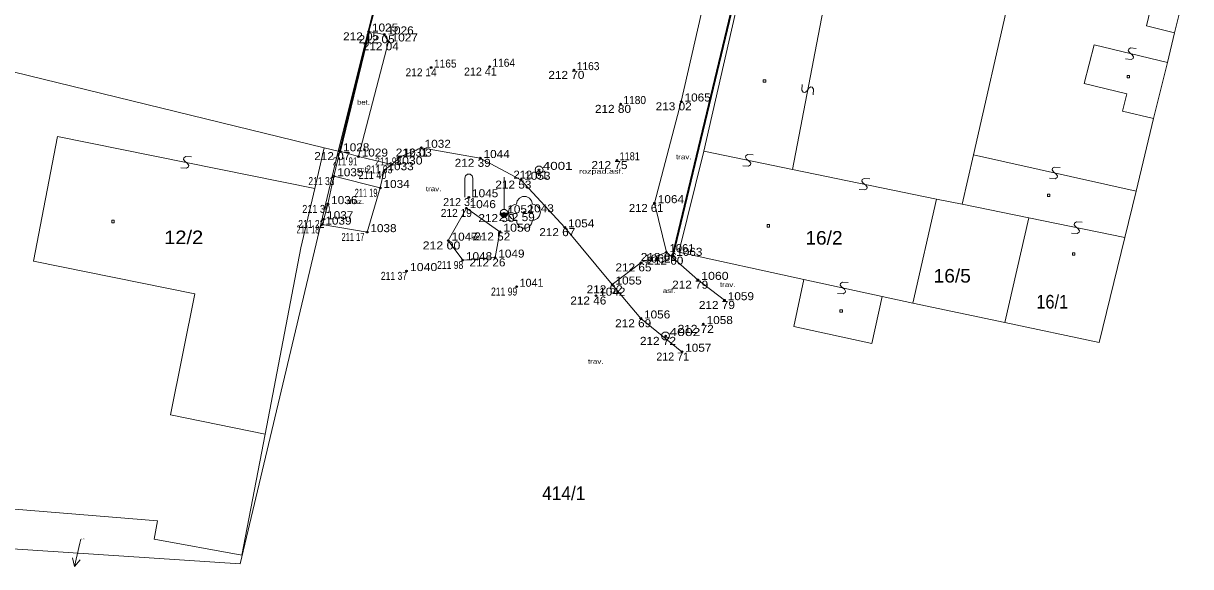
# Model space of a CAD drawing. Extents: x -736847 to -736508, y -1028413 to -1028271.
# Drawn here: x -736680.1 to -736607.2, y -1028365.5 to -1028331.6 of the extents above; entities that cross this region are included whole.
import ezdxf
from ezdxf.enums import TextEntityAlignment as Align

# ---------------------------------------------------------------- set-up
doc = ezdxf.new("R2010")
doc.units = 0
doc.header["$LTSCALE"] = 0.2
doc.header["$PDMODE"] = 32
doc.header["$PDSIZE"] = 0.1
for name, color, linetype, lineweight in [('1', 7, 'Continuous', 13), ('11', 7, 'Continuous', 13), ('12', 7, 'Continuous', 13), ('13', 7, 'Continuous', 13), ('2', 7, 'Continuous', 13), ('6', 7, 'Continuous', 35), ('63', 7, 'Continuous', 13), ('8', 7, 'Continuous', 13)]:
    doc.layers.add(name, color=color, linetype=linetype, lineweight=lineweight)
for name, color, linetype in [('34', 7, 'Continuous'), ('35', 7, 'Continuous'), ('36', 7, 'Continuous'), ('60', 7, 'Continuous')]:
    doc.layers.add(name, color=color, linetype=linetype)

msp = doc.modelspace()

# ---------------------------------------------------------------- linework, layer by layer
at = {"layer": '1'}
for p, q in [((-736657.21, -1028326.51), (-736660.48, -1028339.57)), ((-736607.24, -1028328.06), (-736608.24, -1028332.18)), ((-736620.8, -1028339.79), (-736618.51, -1028329.76)), ((-736632.11, -1028340.7), (-736630.19, -1028330.74)), ((-736608.24, -1028332.18), (-736608.69, -1028334.03)), ((-736613.26, -1028332.92), (-736613.88, -1028335.34)), ((-736608.69, -1028334.03), (-736613.26, -1028332.92)), ((-736661.35, -1028339.36), (-736682.13, -1028334.28)), ((-736608.69, -1028334.03), (-736609.55, -1028337.53)), ((-736613.88, -1028335.34), (-736611.23, -1028335.99)), ((-736611.49, -1028337.06), (-736611.23, -1028335.99)), ((-736609.55, -1028337.53), (-736611.49, -1028337.06)), ((-736609.55, -1028337.53), (-736610.65, -1028342.05)), ((-736678, -1028338.64), (-736679.51, -1028346.43)), ((-736661.94, -1028341.89), (-736678, -1028338.64)), ((-736661.35, -1028339.36), (-736660.48, -1028339.57)), ((-736639.21, -1028345.87), (-736637.65, -1028339.56)), ((-736632.11, -1028340.7), (-736637.65, -1028339.56)), ((-736620.8, -1028339.79), (-736621.5, -1028342.88)), ((-736620.8, -1028339.79), (-736610.65, -1028342.05)), ((-736632.11, -1028340.7), (-736623.11, -1028342.55)), ((-736610.65, -1028342.05), (-736611.36, -1028344.96)), ((-736624.58, -1028349.06), (-736623.11, -1028342.55)), ((-736623.11, -1028342.55), (-736621.5, -1028342.88)), ((-736617.34, -1028343.73), (-736621.5, -1028342.88)), ((-736618.84, -1028350.26), (-736617.34, -1028343.73)), ((-736617.34, -1028343.73), (-736611.36, -1028344.96)), ((-736612.96, -1028351.52), (-736611.36, -1028344.96)), ((-736631.4, -1028347.58), (-736639.21, -1028345.87)), ((-736631.4, -1028347.58), (-736632.03, -1028350.51)), ((-736626.51, -1028348.64), (-736631.4, -1028347.58)), ((-736624.58, -1028349.06), (-736618.84, -1028350.26)), ((-736618.84, -1028350.26), (-736612.96, -1028351.52)), ((-736671.76, -1028362.66), (-736680.68, -1028361.93)), ((-736671.97, -1028363.79), (-736671.76, -1028362.66)), ((-736676.54, -1028363.8), (-736676.6, -1028364.05)), ((-736666.5, -1028364.79), (-736671.97, -1028363.79))]:
    msp.add_line(p, q, dxfattribs=at)
for points in [[(-736637.65, -1028339.56), (-736635.35, -1028329.52), (-736634.27, -1028325.67)], [(-736608.24, -1028332.18), (-736609.99, -1028331.73), (-736609.74, -1028330.69), (-736615.03, -1028329.39), (-736615.32, -1028330.54), (-736618.51, -1028329.76)], [(-736661.35, -1028339.36), (-736661.94, -1028341.89), (-736662.8, -1028345.59)], [(-736660.48, -1028339.57), (-736666.59, -1028365.34), (-736681.13, -1028364.37)], [(-736662.8, -1028345.59), (-736665.04, -1028357.23), (-736666.5, -1028364.79)], [(-736665.04, -1028357.23), (-736670.95, -1028356.03), (-736669.42, -1028348.48), (-736679.51, -1028346.43)], [(-736632.03, -1028350.51), (-736627.15, -1028351.57), (-736626.51, -1028348.64), (-736624.58, -1028349.06)]]:
    msp.add_lwpolyline(points, dxfattribs=at)
at = {"layer": '11'}
for p, q in [((-736647.955, -1028340.73), (-736647.905, -1028340.73)), ((-736640.055, -1028351.11), (-736640.005, -1028351.11))]:
    msp.add_line(p, q, dxfattribs=at)
for points in [[(-736647.855, -1028340.49), (-736647.73, -1028340.58), (-736647.68, -1028340.725), (-736647.73, -1028340.87), (-736647.855, -1028340.96), (-736648.01, -1028340.96), (-736648.135, -1028340.87), (-736648.185, -1028340.725), (-736648.135, -1028340.58), (-736648.01, -1028340.49)], [(-736639.955, -1028350.87), (-736639.83, -1028350.96), (-736639.78, -1028351.105), (-736639.83, -1028351.25), (-736639.955, -1028351.34), (-736640.11, -1028351.34), (-736640.235, -1028351.25), (-736640.285, -1028351.105), (-736640.235, -1028350.96), (-736640.11, -1028350.87)]]:
    msp.add_lwpolyline(points, close=True, dxfattribs=at)
at = {"layer": '12'}
for points in [[(-736647.85, -1028343.38), (-736647.899, -1028343.597), (-736648.038, -1028343.771), (-736648.239, -1028343.867), (-736648.35, -1028343.88), (-736648.399, -1028344.097), (-736648.538, -1028344.271), (-736648.739, -1028344.367), (-736648.961, -1028344.367), (-736649.161, -1028344.271), (-736649.3, -1028344.097), (-736649.35, -1028343.88), (-736649.461, -1028343.867), (-736649.661, -1028343.771), (-736649.8, -1028343.597), (-736649.85, -1028343.38), (-736649.8, -1028343.163), (-736649.661, -1028342.989), (-736649.461, -1028342.892), (-736649.35, -1028342.88), (-736649.3, -1028342.663), (-736649.161, -1028342.489), (-736648.961, -1028342.392), (-736648.739, -1028342.392), (-736648.538, -1028342.489), (-736648.399, -1028342.663), (-736648.35, -1028342.88), (-736648.239, -1028342.892), (-736648.038, -1028342.989), (-736647.899, -1028343.163)], [(-736652.47, -1028343.12), (-736653.6, -1028345.15), (-736652.7, -1028346.37), (-736650.68, -1028346.21), (-736650.38, -1028344.59)]]:
    msp.add_lwpolyline(points, close=True, dxfattribs=at)
msp.add_lwpolyline([(-736648.875, -1028343.38), (-736648.85, -1028343.38), (-736648.825, -1028343.38)], dxfattribs=at)
at = {"layer": '13'}
msp.add_line((-736655.28, -1028339.35), (-736651.6, -1028339.99), dxfattribs=at)
for points in [[(-736636.35, -1028348.87), (-736638.02, -1028347.6), (-736639.98, -1028345.87), (-736640.72, -1028342.81), (-736639.05, -1028336.46), (-736637.34, -1028328.99)], [(-736658.57, -1028332.09), (-736657.6, -1028332.27), (-736657.34, -1028332.71), (-736659.21, -1028339.9)], [(-736657.13, -1028340.4), (-736656.57, -1028339.9), (-736655.28, -1028339.35)], [(-736651.6, -1028339.99), (-736649.06, -1028341.35), (-736646.32, -1028344.32), (-736643.36, -1028347.89), (-736641.58, -1028350.01), (-736639.01, -1028352.09)], [(-736657.85, -1028341.86), (-736658.67, -1028344.62), (-736661.48, -1028344.15)], [(-736643.36, -1028347.89), (-736641.56, -1028346.52), (-736639.98, -1028345.87)]]:
    msp.add_lwpolyline(points, dxfattribs=at)
at = {"layer": '2'}
msp.add_line((-736676.934, -1028365.512), (-736677.066, -1028364.969), dxfattribs=at)
for points in [[(-736610.637, -1028333.145), (-736610.989, -1028333.111), (-736611.11, -1028333.184), (-736611.133, -1028333.282), (-736611.06, -1028333.402), (-736610.889, -1028333.547), (-736610.816, -1028333.667), (-736610.839, -1028333.765), (-736610.96, -1028333.838), (-736611.312, -1028333.804)], [(-736631.495, -1028335.398), (-736631.512, -1028335.751), (-736631.433, -1028335.869), (-736631.335, -1028335.888), (-736631.218, -1028335.808), (-736631.081, -1028335.631), (-736630.964, -1028335.552), (-736630.866, -1028335.57), (-736630.787, -1028335.688), (-736630.804, -1028336.041)], [(-736669.645, -1028339.922), (-736669.998, -1028339.902), (-736670.116, -1028339.98), (-736670.136, -1028340.078), (-736670.058, -1028340.196), (-736669.881, -1028340.333), (-736669.803, -1028340.451), (-736669.823, -1028340.549), (-736669.941, -1028340.627), (-736670.294, -1028340.607)], [(-736634.554, -1028339.788), (-736634.907, -1028339.767), (-736635.025, -1028339.844), (-736635.045, -1028339.942), (-736634.967, -1028340.06), (-736634.792, -1028340.199), (-736634.714, -1028340.317), (-736634.734, -1028340.415), (-736634.852, -1028340.492), (-736635.205, -1028340.471)], [(-736615.394, -1028340.583), (-736615.746, -1028340.556), (-736615.865, -1028340.632), (-736615.887, -1028340.73), (-736615.811, -1028340.849), (-736615.638, -1028340.99), (-736615.562, -1028341.109), (-736615.584, -1028341.207), (-736615.703, -1028341.283), (-736616.055, -1028341.256)], [(-736627.284, -1028341.283), (-736627.637, -1028341.262), (-736627.755, -1028341.339), (-736627.775, -1028341.437), (-736627.697, -1028341.555), (-736627.522, -1028341.694), (-736627.444, -1028341.812), (-736627.464, -1028341.91), (-736627.582, -1028341.987), (-736627.935, -1028341.966)], [(-736614.024, -1028344.003), (-736614.377, -1028343.982), (-736614.495, -1028344.059), (-736614.515, -1028344.157), (-736614.437, -1028344.275), (-736614.262, -1028344.414), (-736614.184, -1028344.532), (-736614.204, -1028344.63), (-736614.322, -1028344.707), (-736614.675, -1028344.686)], [(-736628.625, -1028347.772), (-736628.978, -1028347.746), (-736629.097, -1028347.823), (-736629.118, -1028347.921), (-736629.042, -1028348.039), (-736628.867, -1028348.18), (-736628.791, -1028348.298), (-736628.812, -1028348.396), (-736628.931, -1028348.473), (-736629.284, -1028348.447)], [(-736676.6, -1028364.05), (-736676.934, -1028365.512), (-736676.579, -1028365.08)]]:
    msp.add_lwpolyline(points, dxfattribs=at)
for points in [[(-736633.93, -1028335.1), (-736633.78, -1028335.1), (-736633.78, -1028335.25), (-736633.93, -1028335.25)], [(-736611.21, -1028334.83), (-736611.06, -1028334.83), (-736611.06, -1028334.98), (-736611.21, -1028334.98)], [(-736616.18, -1028342.25), (-736616.03, -1028342.25), (-736616.03, -1028342.4), (-736616.18, -1028342.4)], [(-736674.61, -1028343.88), (-736674.46, -1028343.88), (-736674.46, -1028344.03), (-736674.61, -1028344.03)], [(-736633.69, -1028344.15), (-736633.54, -1028344.15), (-736633.54, -1028344.3), (-736633.69, -1028344.3)], [(-736614.62, -1028345.91), (-736614.47, -1028345.91), (-736614.47, -1028346.06), (-736614.62, -1028346.06)], [(-736629.14, -1028349.47), (-736628.99, -1028349.47), (-736628.99, -1028349.62), (-736629.14, -1028349.62)]]:
    msp.add_lwpolyline(points, close=True, dxfattribs=at)
at = {"layer": '34'}
for p in [(-736658.57, -1028332.09), (-736657.6, -1028332.27), (-736657.34, -1028332.71), (-736654.67, -1028334.34), (-736651.02, -1028334.29), (-736645.75, -1028334.5), (-736642.84, -1028336.62), (-736639.05, -1028336.46), (-736655.28, -1028339.35), (-736660.37, -1028339.57), (-736659.21, -1028339.9), (-736656.57, -1028339.9), (-736651.6, -1028339.99), (-736643.06, -1028340.13), (-736657.6, -1028340.75), (-736657.13, -1028340.4), (-736647.93, -1028340.73), (-736660.74, -1028341.13), (-736649.06, -1028341.35), (-736657.85, -1028341.86), (-736652.32, -1028342.44), (-736661.12, -1028342.87), (-736652.47, -1028343.12), (-736640.72, -1028342.81), (-736661.37, -1028343.81), (-736650.12, -1028343.44), (-736648.85, -1028343.38), (-736661.48, -1028344.15), (-736658.67, -1028344.62), (-736650.38, -1028344.59), (-736646.32, -1028344.32), (-736653.6, -1028345.15), (-736639.98, -1028345.87), (-736639.57, -1028346.1), (-736652.7, -1028346.37), (-736650.68, -1028346.21), (-736641.56, -1028346.52), (-736656.21, -1028347.05), (-736649.33, -1028348.03), (-736643.36, -1028347.89), (-736638.02, -1028347.6), (-736644.38, -1028348.59), (-736636.35, -1028348.87), (-736641.58, -1028350.01), (-736637.67, -1028350.36), (-736640.03, -1028351.11), (-736639.01, -1028352.09)]:
    msp.add_point(p, dxfattribs=at)
at = {"layer": '6'}
for p, q in [((-736639.57, -1028346.1), (-736635.57, -1028329.4)), ((-736658.57, -1028332.09), (-736660.37, -1028339.57))]:
    msp.add_line(p, q, dxfattribs=at)
at = {"layer": '63'}
msp.add_line((-736650.12, -1028343.2), (-736650.12, -1028341.19), dxfattribs=at)
msp.add_lwpolyline([(-736650.04, -1028343.68), (-736650.2, -1028343.68), (-736650.32, -1028343.585), (-736650.36, -1028343.44), (-736650.32, -1028343.295), (-736650.2, -1028343.2), (-736650.04, -1028343.2), (-736649.92, -1028343.295), (-736649.87, -1028343.44), (-736649.92, -1028343.585), (-736650.04, -1028343.68), (-736650.24, -1028343.64), (-736650, -1028343.64), (-736649.96, -1028343.6), (-736650.28, -1028343.6), (-736650.32, -1028343.56), (-736649.92, -1028343.56), (-736649.92, -1028343.52), (-736650.32, -1028343.52), (-736650.32, -1028343.48), (-736649.92, -1028343.48), (-736649.88, -1028343.44), (-736650.36, -1028343.44)], dxfattribs=at)
at = {"layer": '8'}
for p, q in [((-736657.69, -1028328.84), (-736658.57, -1028332.09)), ((-736660.37, -1028339.57), (-736659.21, -1028339.9)), ((-736661.12, -1028342.87), (-736661.37, -1028343.81)), ((-736661.37, -1028343.81), (-736661.48, -1028344.15))]:
    msp.add_line(p, q, dxfattribs=at)
for points in [[(-736660.37, -1028339.57), (-736660.74, -1028341.13), (-736661.12, -1028342.87)], [(-736659.21, -1028339.9), (-736657.13, -1028340.4), (-736657.6, -1028340.75), (-736657.85, -1028341.86), (-736660.74, -1028341.13)], [(-736652.57, -1028342.44), (-736652.569, -1028341.24), (-736652.522, -1028341.093), (-736652.397, -1028341.002), (-736652.242, -1028341.002), (-736652.117, -1028341.093), (-736652.069, -1028341.24), (-736652.07, -1028342.44)]]:
    msp.add_lwpolyline(points, dxfattribs=at)

# ---------------------------------------------------------------- texts
at = {"layer": '2'}
for s, height, width, p in [('12/2', 0.85, 1.1, (-736671.34, -1028345.37)), ('16/2', 0.85, 1.05, (-736631.3, -1028345.4)), ('16/5', 0.85, 1.05, (-736623.29, -1028347.77)), ('16/1', 0.85, 0.9, (-736616.88, -1028349.39)), ('414/1', 0.85, 0.95, (-736647.74, -1028361.35)), ('414/37', 0.05, 1.1, (-736676.54, -1028363.8))]:
    msp.add_text(s, height=height, dxfattribs=dict(at, width=width)).set_placement(p)
at = {"layer": '35'}
for s, width, p in [(' 1025', 1.1, (-736658.57, -1028332.09)), (' 1026', 1.1, (-736657.6, -1028332.27)), (' 1027', 1.1, (-736657.34, -1028332.71)), (' 1165', 0.95, (-736654.67, -1028334.34)), (' 1164', 0.95, (-736651.02, -1028334.29)), (' 1163', 0.95, (-736645.75, -1028334.5)), (' 1180', 0.95, (-736642.84, -1028336.62)), (' 1065', 1.1, (-736639.05, -1028336.46)), (' 1028', 1.1, (-736660.37, -1028339.57)), (' 1029', 1.1, (-736659.21, -1028339.9)), (' 1032', 1.1, (-736655.28, -1028339.35)), (' 1044', 1.1, (-736651.6, -1028339.99)), (' 1033', 1.1, (-736657.6, -1028340.75)), (' 1030', 1.15, (-736657.13, -1028340.4)), (' 4001', 1.25, (-736647.93, -1028340.73)), (' 1181', 0.85, (-736643.06, -1028340.13)), (' 1035', 1.1, (-736660.74, -1028341.13)), (' 1053', 1.1, (-736649.06, -1028341.35)), (' 1034', 1.1, (-736657.85, -1028341.86)), (' 1036', 1.1, (-736661.12, -1028342.87)), (' 1045', 1.1, (-736652.32, -1028342.44)), (' 1064', 1.1, (-736640.72, -1028342.81)), (' 1046', 1.1, (-736652.47, -1028343.12)), (' 1052', 1.1, (-736650.12, -1028343.44)), (' 1043', 1.1, (-736648.85, -1028343.38)), (' 1039', 1.1, (-736661.48, -1028344.15)), (' 1037', 1.1, (-736661.37, -1028343.81)), (' 1054', 1.1, (-736646.32, -1028344.32)), (' 1038', 1.1, (-736658.67, -1028344.62)), (' 1050', 1.15, (-736650.38, -1028344.59)), (' 1047', 1.1, (-736653.6, -1028345.15)), (' 1048', 1.1, (-736652.7, -1028346.37)), (' 1049', 1.1, (-736650.68, -1028346.21)), (' 1062', 1.1, (-736641.56, -1028346.52)), (' 1061', 1.05, (-736639.98, -1028345.87)), (' 1063', 1.1, (-736639.57, -1028346.1)), (' 1040', 1.15, (-736656.21, -1028347.05)), (' 1055', 1.1, (-736643.36, -1028347.89)), (' 1060', 1.15, (-736638.02, -1028347.6)), (' 1042', 1.1, (-736644.38, -1028348.59)), (' 1059', 1.1, (-736636.35, -1028348.87)), (' 1056', 1.1, (-736641.58, -1028350.01)), (' 1058', 1.1, (-736637.67, -1028350.36)), (' 4002', 1.3, (-736640.03, -1028351.11)), (' 1057', 1.1, (-736639.01, -1028352.09))]:
    msp.add_text(s, height=0.5, dxfattribs=dict(at, width=width)).set_placement(p)
for s, p in [(' 1031', (-736656.57, -1028339.9)), (' 1041', (-736649.33, -1028348.03))]:
    msp.add_text(s, height=0.5, dxfattribs=at).set_placement(p)
at = {"layer": '36'}
for s, width, p in [('212 05', 1.1, (-736660.17, -1028332.64)), ('212 05', 1.1, (-736659.2, -1028332.82)), ('212 04', 1.1, (-736658.94, -1028333.26)), ('212 14', 0.95, (-736656.27, -1028334.89)), ('212 70', 1.1, (-736647.35, -1028335.05)), ('213 02', 1.1, (-736640.65, -1028337.01)), ('212 80', 1.1, (-736644.44, -1028337.17)), ('212 03', 1.1, (-736656.88, -1028339.9)), ('212 07', 1.1, (-736661.97, -1028340.12)), ('211 91', 0.75, (-736660.81, -1028340.45)), ('211 98', 0.8, (-736658.17, -1028340.45)), ('212 39', 1.1, (-736653.2, -1028340.54)), ('212 75', 1.1, (-736644.66, -1028340.68)), ('211 40', 0.85, (-736659.2, -1028341.3)), ('211 93', 0.8, (-736658.73, -1028340.95)), ('212 61', 1.05, (-736649.53, -1028341.28)), ('211 33', 0.8, (-736662.34, -1028341.68)), ('212 53', 1.1, (-736650.66, -1028341.9)), ('211 19', 0.7, (-736659.45, -1028342.41)), ('211 30', 0.85, (-736662.72, -1028343.42)), ('212 19', 0.95, (-736654.07, -1028343.67)), ('212 61', 1.05, (-736642.32, -1028343.36)), ('211 22', 0.8, (-736662.97, -1028344.36)), ('212 50', 1.1, (-736651.72, -1028343.99)), ('212 59', 1.1, (-736650.45, -1028343.93)), ('211 18', 0.7, (-736663.08, -1028344.7)), ('212 67', 1.1, (-736647.92, -1028344.87)), ('211 17', 0.7, (-736660.27, -1028345.17)), ('212 00', 1.15, (-736655.2, -1028345.7)), ('212 52', 1.1, (-736651.98, -1028345.14)), ('212 66', 1.1, (-736641.58, -1028346.42)), ('211 98', 0.8, (-736654.3, -1028346.92)), ('212 26', 1.1, (-736652.28, -1028346.76)), ('212 65', 1.1, (-736643.16, -1028347.07)), ('212 60', 1.1, (-736641.17, -1028346.65)), ('211 37', 0.8, (-736657.81, -1028347.6)), ('211 99', 0.8, (-736650.93, -1028348.58)), ('212 52', 1.1, (-736644.96, -1028348.44)), ('212 79', 1.1, (-736639.62, -1028348.15)), ('212 46', 1.1, (-736645.98, -1028349.14)), ('212 79', 1.1, (-736637.95, -1028349.42)), ('212 69', 1.1, (-736643.18, -1028350.56)), ('212 72', 1.1, (-736639.27, -1028350.91)), ('212 72', 1.1, (-736641.63, -1028351.66))]:
    msp.add_text(s, height=0.5, dxfattribs=dict(at, width=width)).set_placement(p)
for s, p in [('212 41', (-736652.62, -1028334.84)), ('212 31', (-736653.92, -1028342.99)), ('212 71', (-736640.61, -1028352.64))]:
    msp.add_text(s, height=0.5, dxfattribs=at).set_placement(p)
at = {"layer": '60'}
for s, width, p in [('bet.', 1.2, (-736658.897, -1028336.657)), ('trav.', 1.25, (-736638.895, -1028340.068)), ('sch.', 1.2, (-736658.87, -1028340.86)), ('rozpad.asf.', 1.4, (-736644.046, -1028340.969)), ('trav.', 1.25, (-736654.515, -1028342.062)), ('dlaz.', 1.25, (-736659.382, -1028342.855)), ('ker', 1.3, (-736651.821, -1028345.08)), ('asf.', 1.2, (-736639.811, -1028348.421)), ('trav.', 1.25, (-736636.149, -1028348.044)), ('trav.', 1.25, (-736644.39, -1028352.84))]:
    msp.add_text(s, height=0.3, dxfattribs=dict(at, width=width)).set_placement(p, align=Align.CENTER)

doc.saveas('drawing.dxf')
